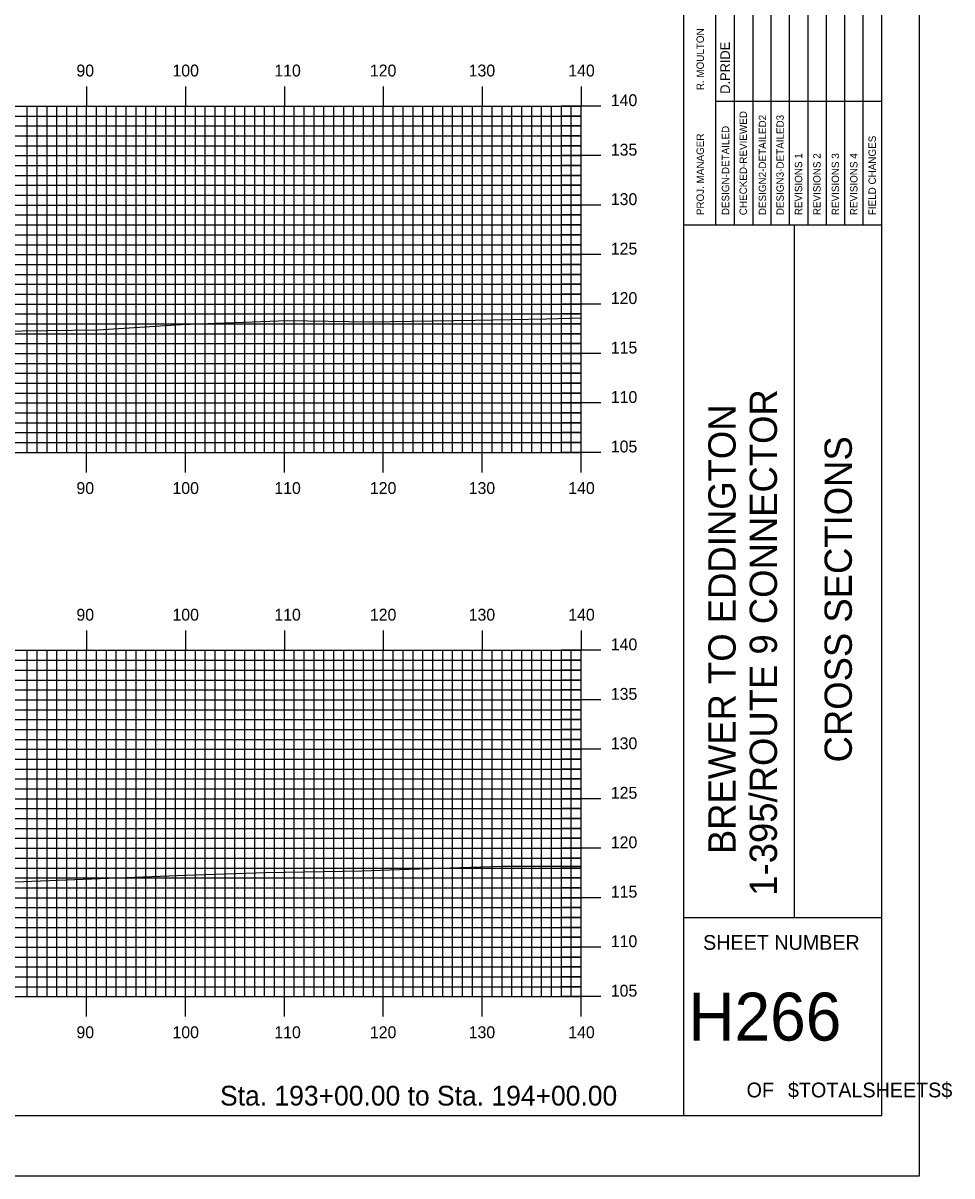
# Model space of a CAD drawing. Extents: x 1788943 to 1789287, y 442591 to 442811.
# Drawn here: x 1789192.7 to 1789286.7, y 442590.5 to 442707.1 of the extents above; entities that cross this region are included whole.
import ezdxf

# ---------------------------------------------------------------- set-up
doc = ezdxf.new("R2010")
doc.units = 0
for name, color, linetype in [('BORDER', 7, 'Continuous'), ('H_V ANNOTATION', 7, 'Continuous'), ('MAJOR', 7, 'Continuous'), ('MINOR', 7, 'Continuous'), ('PLOT BOUNDARY', 7, 'Continuous'), ('S_Roadway_Centerline', 7, 'Continuous')]:
    doc.layers.add(name, color=color, linetype=linetype)

msp = doc.modelspace()

# ---------------------------------------------------------------- linework, layer by layer
at = {"layer": 'BORDER'}
for p, q in [((1789259.56, 442596.67), (1789259.56, 442806.67)), ((1789259.56, 442686.67), (1789279.56, 442686.67)), ((1789270.74, 442616.67), (1789270.74, 442686.67)), ((1789259.56, 442616.67), (1789279.56, 442616.67))]:
    msp.add_line(p, q, dxfattribs=at)
msp.add_lwpolyline([(1788959.56, 442596.67), (1789279.56, 442596.67), (1789279.56, 442806.67), (1788959.56, 442806.67)], close=True, dxfattribs=at)
for points in [[(1789264.65, 442686.68), (1789264.65, 442721.67)], [(1789266.51, 442721.67), (1789266.51, 442686.68)], [(1789268.38, 442686.68), (1789268.38, 442721.67)], [(1789270.24, 442686.68), (1789270.24, 442721.67)], [(1789272.1, 442686.68), (1789272.1, 442721.67)], [(1789273.97, 442686.68), (1789273.97, 442721.67)], [(1789275.83, 442686.68), (1789275.83, 442721.67)], [(1789277.69, 442686.68), (1789277.69, 442721.67)], [(1789262.79, 442686.68), (1789262.79, 442720.26)], [(1789262.79, 442699.17), (1789279.56, 442699.17)]]:
    msp.add_lwpolyline(points, dxfattribs=at)
at = {"layer": 'MAJOR'}
for p, q in [((1789199.16, 442700.67), (1789199.16, 442698.67)), ((1789209.16, 442700.67), (1789209.16, 442698.67)), ((1789219.16, 442700.67), (1789219.16, 442698.67)), ((1789229.16, 442700.67), (1789229.16, 442698.67)), ((1789239.16, 442700.67), (1789239.16, 442698.67)), ((1789249.16, 442700.67), (1789249.16, 442698.67)), ((1788969.16, 442698.67), (1789249.16, 442698.67)), ((1788969.16, 442698.67), (1789249.16, 442698.67)), ((1789199.16, 442663.67), (1789199.16, 442698.67)), ((1789209.16, 442663.67), (1789209.16, 442698.67)), ((1789219.16, 442663.67), (1789219.16, 442698.67)), ((1789229.16, 442663.67), (1789229.16, 442698.67)), ((1789239.16, 442663.67), (1789239.16, 442698.67)), ((1789251.16, 442698.67), (1789247.15, 442698.67)), ((1789249.16, 442663.67), (1789249.16, 442698.67)), ((1789249.16, 442663.67), (1789249.16, 442698.67)), ((1788969.16, 442693.67), (1789249.16, 442693.67)), ((1789251.16, 442693.67), (1789247.15, 442693.67)), ((1788969.16, 442688.67), (1789249.16, 442688.67)), ((1789251.16, 442688.67), (1789247.15, 442688.67)), ((1788969.16, 442683.67), (1789249.16, 442683.67)), ((1789251.16, 442683.67), (1789247.15, 442683.67)), ((1788969.16, 442678.67), (1789249.16, 442678.67)), ((1789251.16, 442678.67), (1789247.15, 442678.67)), ((1788969.16, 442673.67), (1789249.16, 442673.67)), ((1789251.16, 442673.67), (1789247.15, 442673.67)), ((1788969.16, 442668.67), (1789249.16, 442668.67)), ((1789251.16, 442668.67), (1789247.15, 442668.67)), ((1788969.16, 442663.67), (1789249.16, 442663.67)), ((1788969.16, 442663.67), (1789249.16, 442663.67)), ((1789199.16, 442661.66), (1789199.16, 442663.67)), ((1789209.16, 442661.66), (1789209.16, 442663.67)), ((1789219.16, 442661.66), (1789219.16, 442663.67)), ((1789229.16, 442661.66), (1789229.16, 442663.67)), ((1789239.16, 442661.66), (1789239.16, 442663.67)), ((1789251.16, 442663.67), (1789247.15, 442663.67)), ((1789249.16, 442661.66), (1789249.16, 442663.67)), ((1789199.16, 442645.67), (1789199.16, 442643.67)), ((1789209.16, 442645.67), (1789209.16, 442643.67)), ((1789219.16, 442645.67), (1789219.16, 442643.67)), ((1789229.16, 442645.67), (1789229.16, 442643.67)), ((1789239.16, 442645.67), (1789239.16, 442643.67)), ((1789249.16, 442645.67), (1789249.16, 442643.67)), ((1788969.16, 442643.67), (1789249.16, 442643.67)), ((1788969.16, 442643.67), (1789249.16, 442643.67)), ((1789199.16, 442608.67), (1789199.16, 442643.67)), ((1789209.16, 442608.67), (1789209.16, 442643.67)), ((1789219.16, 442608.67), (1789219.16, 442643.67)), ((1789229.16, 442608.67), (1789229.16, 442643.67)), ((1789239.16, 442608.67), (1789239.16, 442643.67)), ((1789251.16, 442643.67), (1789247.15, 442643.67)), ((1789249.16, 442608.67), (1789249.16, 442643.67)), ((1789249.16, 442608.67), (1789249.16, 442643.67)), ((1788969.16, 442638.67), (1789249.16, 442638.67)), ((1789251.16, 442638.67), (1789247.15, 442638.67)), ((1788969.16, 442633.67), (1789249.16, 442633.67)), ((1789251.16, 442633.67), (1789247.15, 442633.67)), ((1788969.16, 442628.67), (1789249.16, 442628.67)), ((1789251.16, 442628.67), (1789247.15, 442628.67)), ((1788969.16, 442623.67), (1789249.16, 442623.67)), ((1789251.16, 442623.67), (1789247.15, 442623.67)), ((1788969.16, 442618.67), (1789249.16, 442618.67)), ((1789251.16, 442618.67), (1789247.15, 442618.67)), ((1788969.16, 442613.67), (1789249.16, 442613.67)), ((1789251.16, 442613.67), (1789247.15, 442613.67)), ((1788969.16, 442608.67), (1789249.16, 442608.67)), ((1788969.16, 442608.67), (1789249.16, 442608.67)), ((1789199.16, 442606.66), (1789199.16, 442608.67)), ((1789209.16, 442606.66), (1789209.16, 442608.67)), ((1789219.16, 442606.66), (1789219.16, 442608.67)), ((1789229.16, 442606.66), (1789229.16, 442608.67)), ((1789239.16, 442606.66), (1789239.16, 442608.67)), ((1789251.16, 442608.67), (1789247.15, 442608.67)), ((1789249.16, 442606.66), (1789249.16, 442608.67))]:
    msp.add_line(p, q, dxfattribs=at)
at = {"layer": 'MINOR'}
for p, q in [((1789193.16, 442663.67), (1789193.16, 442698.67)), ((1789194.16, 442663.67), (1789194.16, 442698.67)), ((1789195.16, 442663.67), (1789195.16, 442698.67)), ((1789196.16, 442663.67), (1789196.16, 442698.67)), ((1789197.16, 442663.67), (1789197.16, 442698.67)), ((1789198.16, 442663.67), (1789198.16, 442698.67)), ((1789200.16, 442663.67), (1789200.16, 442698.67)), ((1789201.16, 442663.67), (1789201.16, 442698.67)), ((1789202.16, 442663.67), (1789202.16, 442698.67)), ((1789203.16, 442663.67), (1789203.16, 442698.67)), ((1789204.16, 442663.67), (1789204.16, 442698.67)), ((1789205.16, 442663.67), (1789205.16, 442698.67)), ((1789206.16, 442663.67), (1789206.16, 442698.67)), ((1789207.16, 442663.67), (1789207.16, 442698.67)), ((1789208.16, 442663.67), (1789208.16, 442698.67)), ((1789210.16, 442663.67), (1789210.16, 442698.67)), ((1789211.16, 442663.67), (1789211.16, 442698.67)), ((1789212.16, 442663.67), (1789212.16, 442698.67)), ((1789213.16, 442663.67), (1789213.16, 442698.67)), ((1789214.16, 442663.67), (1789214.16, 442698.67)), ((1789215.16, 442663.67), (1789215.16, 442698.67)), ((1789216.16, 442663.67), (1789216.16, 442698.67)), ((1789217.16, 442663.67), (1789217.16, 442698.67)), ((1789218.16, 442663.67), (1789218.16, 442698.67)), ((1789220.16, 442663.67), (1789220.16, 442698.67)), ((1789221.16, 442663.67), (1789221.16, 442698.67)), ((1789222.16, 442663.67), (1789222.16, 442698.67)), ((1789223.16, 442663.67), (1789223.16, 442698.67)), ((1789224.16, 442663.67), (1789224.16, 442698.67)), ((1789225.16, 442663.67), (1789225.16, 442698.67)), ((1789226.16, 442663.67), (1789226.16, 442698.67)), ((1789227.16, 442663.67), (1789227.16, 442698.67)), ((1789228.16, 442663.67), (1789228.16, 442698.67)), ((1789230.16, 442663.67), (1789230.16, 442698.67)), ((1789231.16, 442663.67), (1789231.16, 442698.67)), ((1789232.16, 442663.67), (1789232.16, 442698.67)), ((1789233.16, 442663.67), (1789233.16, 442698.67)), ((1789234.16, 442663.67), (1789234.16, 442698.67)), ((1789235.16, 442663.67), (1789235.16, 442698.67)), ((1789236.16, 442663.67), (1789236.16, 442698.67)), ((1789237.16, 442663.67), (1789237.16, 442698.67)), ((1789238.16, 442663.67), (1789238.16, 442698.67)), ((1789240.16, 442663.67), (1789240.16, 442698.67)), ((1789241.16, 442663.67), (1789241.16, 442698.67)), ((1789242.16, 442663.67), (1789242.16, 442698.67)), ((1789243.16, 442663.67), (1789243.16, 442698.67)), ((1789244.16, 442663.67), (1789244.16, 442698.67)), ((1789245.16, 442663.67), (1789245.16, 442698.67)), ((1789246.16, 442663.67), (1789246.16, 442698.67)), ((1789247.16, 442663.67), (1789247.16, 442698.67)), ((1789248.16, 442663.67), (1789248.16, 442698.67)), ((1788969.16, 442697.67), (1789249.16, 442697.67)), ((1789249.16, 442697.67), (1789247.15, 442697.67)), ((1788969.16, 442696.67), (1789249.16, 442696.67)), ((1789249.16, 442696.67), (1789247.15, 442696.67)), ((1788969.16, 442695.67), (1789249.16, 442695.67)), ((1789249.16, 442695.67), (1789247.15, 442695.67)), ((1788969.16, 442694.67), (1789249.16, 442694.67)), ((1789249.16, 442694.67), (1789247.15, 442694.67)), ((1788969.16, 442692.67), (1789249.16, 442692.67)), ((1789249.16, 442692.67), (1789247.15, 442692.67)), ((1788969.16, 442691.67), (1789249.16, 442691.67)), ((1789249.16, 442691.67), (1789247.15, 442691.67)), ((1788969.16, 442690.67), (1789249.16, 442690.67)), ((1789249.16, 442690.67), (1789247.15, 442690.67)), ((1788969.16, 442689.67), (1789249.16, 442689.67)), ((1789249.16, 442689.67), (1789247.15, 442689.67)), ((1788969.16, 442687.67), (1789249.16, 442687.67)), ((1789249.16, 442687.67), (1789247.15, 442687.67)), ((1788969.16, 442686.67), (1789249.16, 442686.67)), ((1788969.16, 442685.67), (1789249.16, 442685.67)), ((1789249.16, 442686.67), (1789247.15, 442686.67)), ((1789249.16, 442685.67), (1789247.15, 442685.67)), ((1788969.16, 442684.67), (1789249.16, 442684.67)), ((1789249.16, 442684.67), (1789247.15, 442684.67)), ((1788969.16, 442682.67), (1789249.16, 442682.67)), ((1789249.16, 442682.67), (1789247.15, 442682.67)), ((1788969.16, 442681.67), (1789249.16, 442681.67)), ((1789249.16, 442681.67), (1789247.15, 442681.67)), ((1788969.16, 442680.67), (1789249.16, 442680.67)), ((1789249.16, 442680.67), (1789247.15, 442680.67)), ((1788969.16, 442679.67), (1789249.16, 442679.67)), ((1789249.16, 442679.67), (1789247.15, 442679.67)), ((1788969.16, 442677.67), (1789249.16, 442677.67)), ((1789249.16, 442677.67), (1789247.15, 442677.67)), ((1788969.16, 442676.67), (1789249.16, 442676.67)), ((1789249.16, 442676.67), (1789247.15, 442676.67)), ((1788969.16, 442675.67), (1789249.16, 442675.67)), ((1789249.16, 442675.67), (1789247.15, 442675.67)), ((1788969.16, 442674.67), (1789249.16, 442674.67)), ((1789249.16, 442674.67), (1789247.15, 442674.67)), ((1788969.16, 442672.67), (1789249.16, 442672.67)), ((1788969.16, 442671.67), (1789249.16, 442671.67)), ((1789249.16, 442672.67), (1789247.15, 442672.67)), ((1789249.16, 442671.67), (1789247.15, 442671.67)), ((1788969.16, 442670.67), (1789249.16, 442670.67)), ((1789249.16, 442670.67), (1789247.15, 442670.67)), ((1788969.16, 442669.67), (1789249.16, 442669.67)), ((1789249.16, 442669.67), (1789247.15, 442669.67)), ((1788969.16, 442667.67), (1789249.16, 442667.67)), ((1789249.16, 442667.67), (1789247.15, 442667.67)), ((1788969.16, 442666.67), (1789249.16, 442666.67)), ((1789249.16, 442666.67), (1789247.15, 442666.67)), ((1788969.16, 442665.67), (1789249.16, 442665.67)), ((1788969.16, 442664.67), (1789249.16, 442664.67)), ((1789249.16, 442665.67), (1789247.15, 442665.67)), ((1789249.16, 442664.67), (1789247.15, 442664.67)), ((1789193.16, 442608.67), (1789193.16, 442643.67)), ((1789194.16, 442608.67), (1789194.16, 442643.67)), ((1789195.16, 442608.67), (1789195.16, 442643.67)), ((1789196.16, 442608.67), (1789196.16, 442643.67)), ((1789197.16, 442608.67), (1789197.16, 442643.67)), ((1789198.16, 442608.67), (1789198.16, 442643.67)), ((1789200.16, 442608.67), (1789200.16, 442643.67)), ((1789201.16, 442608.67), (1789201.16, 442643.67)), ((1789202.16, 442608.67), (1789202.16, 442643.67)), ((1789203.16, 442608.67), (1789203.16, 442643.67)), ((1789204.16, 442608.67), (1789204.16, 442643.67)), ((1789205.16, 442608.67), (1789205.16, 442643.67)), ((1789206.16, 442608.67), (1789206.16, 442643.67)), ((1789207.16, 442608.67), (1789207.16, 442643.67)), ((1789208.16, 442608.67), (1789208.16, 442643.67)), ((1789210.16, 442608.67), (1789210.16, 442643.67)), ((1789211.16, 442608.67), (1789211.16, 442643.67)), ((1789212.16, 442608.67), (1789212.16, 442643.67)), ((1789213.16, 442608.67), (1789213.16, 442643.67)), ((1789214.16, 442608.67), (1789214.16, 442643.67)), ((1789215.16, 442608.67), (1789215.16, 442643.67)), ((1789216.16, 442608.67), (1789216.16, 442643.67)), ((1789217.16, 442608.67), (1789217.16, 442643.67)), ((1789218.16, 442608.67), (1789218.16, 442643.67)), ((1789220.16, 442608.67), (1789220.16, 442643.67)), ((1789221.16, 442608.67), (1789221.16, 442643.67)), ((1789222.16, 442608.67), (1789222.16, 442643.67)), ((1789223.16, 442608.67), (1789223.16, 442643.67)), ((1789224.16, 442608.67), (1789224.16, 442643.67)), ((1789225.16, 442608.67), (1789225.16, 442643.67)), ((1789226.16, 442608.67), (1789226.16, 442643.67)), ((1789227.16, 442608.67), (1789227.16, 442643.67)), ((1789228.16, 442608.67), (1789228.16, 442643.67)), ((1789230.16, 442608.67), (1789230.16, 442643.67)), ((1789231.16, 442608.67), (1789231.16, 442643.67)), ((1789232.16, 442608.67), (1789232.16, 442643.67)), ((1789233.16, 442608.67), (1789233.16, 442643.67)), ((1789234.16, 442608.67), (1789234.16, 442643.67)), ((1789235.16, 442608.67), (1789235.16, 442643.67)), ((1789236.16, 442608.67), (1789236.16, 442643.67)), ((1789237.16, 442608.67), (1789237.16, 442643.67)), ((1789238.16, 442608.67), (1789238.16, 442643.67)), ((1789240.16, 442608.67), (1789240.16, 442643.67)), ((1789241.16, 442608.67), (1789241.16, 442643.67)), ((1789242.16, 442608.67), (1789242.16, 442643.67)), ((1789243.16, 442608.67), (1789243.16, 442643.67)), ((1789244.16, 442608.67), (1789244.16, 442643.67)), ((1789245.16, 442608.67), (1789245.16, 442643.67)), ((1789246.16, 442608.67), (1789246.16, 442643.67)), ((1789247.16, 442608.67), (1789247.16, 442643.67)), ((1789248.16, 442608.67), (1789248.16, 442643.67)), ((1788969.16, 442642.67), (1789249.16, 442642.67)), ((1789249.16, 442642.67), (1789247.15, 442642.67)), ((1788969.16, 442641.67), (1789249.16, 442641.67)), ((1789249.16, 442641.67), (1789247.15, 442641.67)), ((1788969.16, 442640.67), (1789249.16, 442640.67)), ((1789249.16, 442640.67), (1789247.15, 442640.67)), ((1788969.16, 442639.67), (1789249.16, 442639.67)), ((1789249.16, 442639.67), (1789247.15, 442639.67)), ((1788969.16, 442637.67), (1789249.16, 442637.67)), ((1789249.16, 442637.67), (1789247.15, 442637.67)), ((1788969.16, 442636.67), (1789249.16, 442636.67)), ((1788969.16, 442635.67), (1789249.16, 442635.67)), ((1789249.16, 442636.67), (1789247.15, 442636.67)), ((1789249.16, 442635.67), (1789247.15, 442635.67)), ((1788969.16, 442634.67), (1789249.16, 442634.67)), ((1789249.16, 442634.67), (1789247.15, 442634.67)), ((1788969.16, 442632.67), (1789249.16, 442632.67)), ((1789249.16, 442632.67), (1789247.15, 442632.67)), ((1788969.16, 442631.67), (1789249.16, 442631.67)), ((1789249.16, 442631.67), (1789247.15, 442631.67)), ((1788969.16, 442630.67), (1789249.16, 442630.67)), ((1789249.16, 442630.67), (1789247.15, 442630.67)), ((1788969.16, 442629.67), (1789249.16, 442629.67)), ((1789249.16, 442629.67), (1789247.15, 442629.67)), ((1788969.16, 442627.67), (1789249.16, 442627.67)), ((1789249.16, 442627.67), (1789247.15, 442627.67)), ((1788969.16, 442626.67), (1789249.16, 442626.67)), ((1789249.16, 442626.67), (1789247.15, 442626.67)), ((1788969.16, 442625.67), (1789249.16, 442625.67)), ((1789249.16, 442625.67), (1789247.15, 442625.67)), ((1788969.16, 442624.67), (1789249.16, 442624.67)), ((1789249.16, 442624.67), (1789247.15, 442624.67)), ((1788969.16, 442622.67), (1789249.16, 442622.67)), ((1788969.16, 442621.67), (1789249.16, 442621.67)), ((1789249.16, 442622.67), (1789247.15, 442622.67)), ((1789249.16, 442621.67), (1789247.15, 442621.67)), ((1788969.16, 442620.67), (1789249.16, 442620.67)), ((1789249.16, 442620.67), (1789247.15, 442620.67)), ((1788969.16, 442619.67), (1789249.16, 442619.67)), ((1789249.16, 442619.67), (1789247.15, 442619.67)), ((1788969.16, 442617.67), (1789249.16, 442617.67)), ((1789249.16, 442617.67), (1789247.15, 442617.67)), ((1788969.16, 442616.67), (1789249.16, 442616.67)), ((1789249.16, 442616.67), (1789247.15, 442616.67)), ((1788969.16, 442615.67), (1789249.16, 442615.67)), ((1788969.16, 442614.67), (1789249.16, 442614.67)), ((1789249.16, 442615.67), (1789247.15, 442615.67)), ((1789249.16, 442614.67), (1789247.15, 442614.67)), ((1788969.16, 442612.67), (1789249.16, 442612.67)), ((1789249.16, 442612.67), (1789247.15, 442612.67)), ((1788969.16, 442611.67), (1789249.16, 442611.67)), ((1789249.16, 442611.67), (1789247.15, 442611.67)), ((1788969.16, 442610.67), (1789249.16, 442610.67)), ((1789249.16, 442610.67), (1789247.15, 442610.67)), ((1788969.16, 442609.67), (1789249.16, 442609.67)), ((1789249.16, 442609.67), (1789247.15, 442609.67))]:
    msp.add_line(p, q, dxfattribs=at)
at = {"layer": 'PLOT BOUNDARY'}
msp.add_lwpolyline([(1788943.37, 442590.55), (1789283.37, 442590.55), (1789283.37, 442810.55), (1788943.37, 442810.55)], close=True, dxfattribs=at)
at = {"layer": 'S_Roadway_Centerline'}
for points in [[(1789184.99, 442675.85), (1789200.31, 442676.07), (1789208.73, 442676.59), (1789219.48, 442677), (1789227.73, 442676.87), (1789238.43, 442677.03), (1789245.67, 442677.19), (1789249.16, 442677.29)], [(1789055.18, 442618.67), (1789079.24, 442619.18), (1789090, 442619.25), (1789094.85, 442619.28), (1789097.58, 442619.36), (1789105.6, 442619.33), (1789115.71, 442619.4), (1789123.61, 442619.41), (1789130.99, 442619.59), (1789134.36, 442619.59), (1789143.62, 442619.84), (1789153.54, 442619.9), (1789168.57, 442620.2), (1789171.91, 442620.38), (1789182.58, 442620.25), (1789189.54, 442620.34), (1789191.9, 442620.26), (1789209.18, 442620.94), (1789217.28, 442621.21), (1789226.98, 442621.37), (1789231.78, 442621.56), (1789241.11, 442621.85), (1789249.16, 442621.85)]]:
    msp.add_lwpolyline(points, dxfattribs=at)

# ---------------------------------------------------------------- texts
at = {"layer": 'BORDER'}
for s, height, p in [('R. MOULTON', 0.745, (1789261.57, 442700.28)), ('D.PRIDE', 0.969, (1789264.2, 442699.92)), ('CHECKED-REVIEWED', 0.7455, (1789265.92, 442687.65)), ('DESIGN2-DETAILED2', 0.7455, (1789267.86, 442687.65)), ('DESIGN3-DETAILED3', 0.7455, (1789269.65, 442687.65)), ('DESIGN-DETAILED', 0.7455, (1789264.13, 442687.65)), ('PROJ. MANAGER', 0.7455, (1789261.57, 442687.65)), ('FIELD CHANGES', 0.7455, (1789278.96, 442687.65)), ('REVISIONS 1', 0.7455, (1789271.51, 442687.65)), ('REVISIONS 2', 0.7455, (1789273.37, 442687.65)), ('REVISIONS 3', 0.7455, (1789275.24, 442687.65)), ('REVISIONS 4', 0.7455, (1789277.1, 442687.65)), ('1-395/ROUTE 9 CONNECTOR', 2.7557, (1789268.96, 442618.87)), ('BREWER TO EDDINGTON', 2.7557, (1789264.78, 442623.07)), ('CROSS SECTIONS', 2.7557, (1789276.53, 442632.34))]:
    msp.add_text(s, height=height, rotation=90, dxfattribs=at).set_placement(p)
for s, height, p in [('SHEET NUMBER', 1.4905, (1789261.49, 442613.4)), ('H266', 4.839, (1789260, 442604.23)), ('OF', 1.491, (1789265.89, 442598.49)), ('$TOTALSHEETS$', 1.4905, (1789270.07, 442598.49))]:
    msp.add_text(s, height=height, dxfattribs=at).set_placement(p)
at = {"layer": 'H_V ANNOTATION'}
for s, height, p in [('90', 1.2, (1789198.13, 442701.67)), ('100', 1.2, (1789207.84, 442701.67)), ('110', 1.2, (1789218.14, 442701.67)), ('120', 1.2, (1789227.8, 442701.67)), ('130', 1.2, (1789237.79, 442701.67)), ('140', 1.2, (1789247.86, 442701.67)), ('140', 1.2, (1789252.16, 442698.67)), ('135', 1.2, (1789252.16, 442693.67)), ('130', 1.2, (1789252.16, 442688.67)), ('125', 1.2, (1789252.16, 442683.67)), ('120', 1.2, (1789252.16, 442678.67)), ('115', 1.2, (1789252.16, 442673.67)), ('110', 1.2, (1789252.16, 442668.67)), ('105', 1.2, (1789252.16, 442663.67)), ('90', 1.2, (1789198.13, 442659.47)), ('100', 1.2, (1789207.84, 442659.47)), ('110', 1.2, (1789218.14, 442659.47)), ('120', 1.2, (1789227.8, 442659.47)), ('130', 1.2, (1789237.79, 442659.47)), ('140', 1.2, (1789247.86, 442659.47)), ('90', 1.2, (1789198.13, 442646.67)), ('100', 1.2, (1789207.84, 442646.67)), ('110', 1.2, (1789218.14, 442646.67)), ('120', 1.2, (1789227.8, 442646.67)), ('130', 1.2, (1789237.79, 442646.67)), ('140', 1.2, (1789247.86, 442646.67)), ('140', 1.2, (1789252.16, 442643.67)), ('135', 1.2, (1789252.16, 442638.67)), ('130', 1.2, (1789252.16, 442633.67)), ('125', 1.2, (1789252.16, 442628.67)), ('120', 1.2, (1789252.16, 442623.67)), ('115', 1.2, (1789252.16, 442618.67)), ('110', 1.2, (1789252.16, 442613.67)), ('105', 1.2, (1789252.16, 442608.67)), ('90', 1.2, (1789198.13, 442604.47)), ('100', 1.2, (1789207.84, 442604.47)), ('110', 1.2, (1789218.14, 442604.47)), ('120', 1.2, (1789227.8, 442604.47)), ('130', 1.2, (1789237.79, 442604.47)), ('140', 1.2, (1789247.86, 442604.47)), ('Sta. 193+00.00 to Sta. 194+00.00', 2.0004, (1789212.65, 442597.66))]:
    msp.add_text(s, height=height, dxfattribs=at).set_placement(p)

doc.saveas('drawing.dxf')
